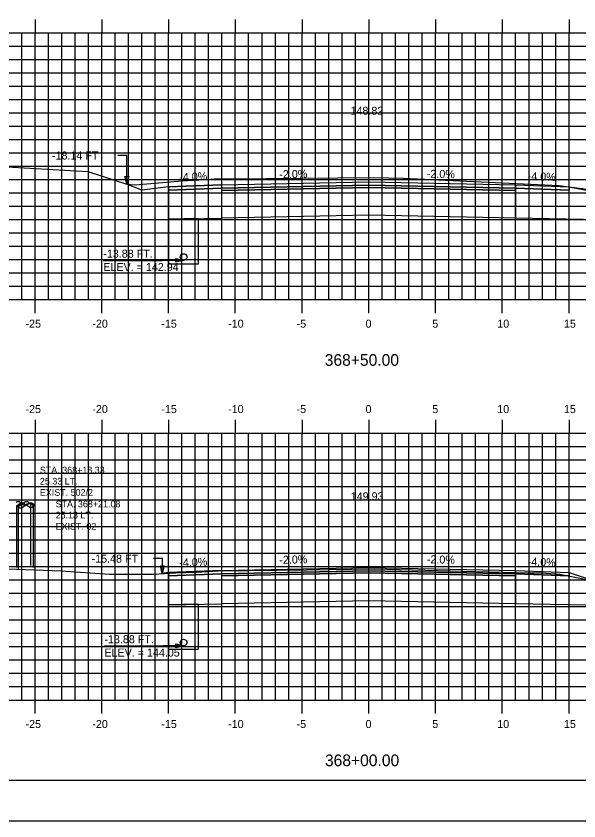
# Model space of a CAD drawing. Extents: x 1147855 to 1148025, y 608981 to 609091.
# Drawn here: x 1147911.8 to 1147953.9, y 608981.3 to 609041.6 of the extents above; entities that cross this region are included whole.
import ezdxf

# ---------------------------------------------------------------- set-up
doc = ezdxf.new("R2010")
doc.units = 0
for name, color, linetype in [('ANNOTATION', 7, 'Continuous'), ('BORDER', 7, 'Continuous'), ('D_Drainage_Underdrain', 7, 'Continuous'), ('D_Drainage_Underdrain_06in', 7, 'Continuous'), ('D_Roadway_Centerline', 7, 'Continuous'), ('D_Roadway_Centerline_Text', 7, 'Continuous'), ('D_Roadway_Edge_Shoulder', 7, 'Continuous'), ('D_Roadway_Edge_TW', 7, 'Continuous'), ('D_Roadway_Pavement', 7, 'Continuous'), ('D_Roadway_SlopeLines', 7, 'Continuous'), ('D_Roadway_SubGrade', 7, 'Continuous'), ('D_Text_Monospaced', 7, 'Continuous'), ('D_Text_Standard', 7, 'Continuous'), ('D_Utilities_Pole_Joint', 7, 'Continuous'), ('H_V ANNOTATION', 7, 'Continuous'), ('MAJOR', 7, 'Continuous'), ('MINOR', 7, 'Continuous'), ('PLOT BOUNDARY', 7, 'Continuous'), ('S_Roadway_Centerline', 7, 'Continuous'), ('S_Utilities_Pole_Power', 7, 'Continuous')]:
    doc.layers.add(name, color=color, linetype=linetype)

msp = doc.modelspace()

# ---------------------------------------------------------------- linework, layer by layer
for points in [[(1147923.21, 609028.779), (1147923.211, 609028.779), (1147927.211, 609028.939), (1147938.211, 609029.159), (1147949.211, 609028.939), (1147953.211, 609028.779), (1147966.938, 609026.085), (1147967.48, 609025.978), (1147968.704, 609026.54), (1147969.928, 609026.999), (1147971.152, 609027.357), (1147972.377, 609027.613)], [(1147922.727, 608999.809), (1147923.21, 608999.889), (1147923.211, 608999.889), (1147927.211, 609000.049), (1147938.211, 609000.269), (1147949.211, 609000.049), (1147953.211, 608999.889), (1147960.934, 608997.315), (1147963.934, 608996.315), (1147963.962, 608996.329), (1147965.212, 608996.889), (1147966.462, 608997.318), (1147967.712, 608997.616), (1147968.962, 608997.784)]]:
    msp.add_lwpolyline(points)
at = {"layer": 'BORDER'}
msp.add_lwpolyline([(1147863.211, 608984.335), (1148023.211, 608984.335), (1148023.211, 609089.335), (1147863.211, 609089.335)], close=True, dxfattribs=at)
at = {"layer": 'D_Drainage_Underdrain'}
for points in [[(1147923.211, 609026.359), (1147923.211, 609023.029), (1147925.461, 609023.029), (1147925.461, 609026.404)], [(1147923.211, 608997.469), (1147923.211, 608994.139), (1147925.461, 608994.139), (1147925.461, 608997.514)]]:
    msp.add_lwpolyline(points, close=True, dxfattribs=at)
at = {"layer": 'D_Drainage_Underdrain_06in'}
for points in [[(1147924.336, 609023.779), (1147924.413, 609023.767), (1147924.482, 609023.731), (1147924.538, 609023.676), (1147924.573, 609023.606), (1147924.586, 609023.529), (1147924.573, 609023.452), (1147924.538, 609023.382), (1147924.482, 609023.327), (1147924.413, 609023.291), (1147924.336, 609023.279), (1147924.258, 609023.291), (1147924.189, 609023.327), (1147924.133, 609023.382), (1147924.098, 609023.452), (1147924.086, 609023.529), (1147924.098, 609023.606), (1147924.133, 609023.676), (1147924.189, 609023.731), (1147924.258, 609023.767)], [(1147924.336, 608994.889), (1147924.413, 608994.877), (1147924.482, 608994.841), (1147924.538, 608994.786), (1147924.573, 608994.716), (1147924.586, 608994.639), (1147924.573, 608994.562), (1147924.538, 608994.492), (1147924.482, 608994.437), (1147924.413, 608994.401), (1147924.336, 608994.389), (1147924.258, 608994.401), (1147924.189, 608994.437), (1147924.133, 608994.492), (1147924.098, 608994.562), (1147924.086, 608994.639), (1147924.098, 608994.716), (1147924.133, 608994.786), (1147924.189, 608994.841), (1147924.258, 608994.877)]]:
    msp.add_lwpolyline(points, close=True, dxfattribs=at)
at = {"layer": 'D_Roadway_Edge_Shoulder'}
for points in [[(1147927.211, 609028.939), (1147923.211, 609028.779), (1147923.211, 609028.529), (1147927.211, 609028.689)], [(1147949.211, 609028.939), (1147953.211, 609028.779), (1147953.211, 609028.529), (1147949.211, 609028.689)], [(1147927.211, 609000.049), (1147923.211, 608999.889), (1147923.211, 608999.639), (1147927.211, 608999.799)], [(1147949.211, 609000.049), (1147953.211, 608999.889), (1147953.211, 608999.639), (1147949.211, 608999.799)]]:
    msp.add_lwpolyline(points, close=True, dxfattribs=at)
at = {"layer": 'D_Roadway_Edge_TW'}
for points in [[(1147927.211, 609028.689), (1147927.211, 609028.939), (1147938.211, 609029.159), (1147949.211, 609028.939), (1147949.211, 609028.689), (1147938.211, 609028.909)], [(1147927.211, 608999.799), (1147927.211, 609000.049), (1147938.211, 609000.269), (1147949.211, 609000.049), (1147949.211, 608999.799), (1147938.211, 609000.019)]]:
    msp.add_lwpolyline(points, close=True, dxfattribs=at)
at = {"layer": 'D_Roadway_Pavement'}
for points in [[(1147927.211, 609028.523), (1147927.211, 609028.689), (1147938.211, 609028.909), (1147949.211, 609028.689), (1147949.211, 609028.523), (1147938.211, 609028.743)], [(1147927.211, 608999.633), (1147927.211, 608999.799), (1147938.211, 609000.019), (1147949.211, 608999.799), (1147949.211, 608999.633), (1147938.211, 608999.853)]]:
    msp.add_lwpolyline(points, close=True, dxfattribs=at)
at = {"layer": 'D_Roadway_SlopeLines'}
for p, q in [((1147921.211, 609028.529), (1147920.071, 609028.98)), ((1147923.211, 609028.779), (1147921.211, 609028.529))]:
    msp.add_line(p, q, dxfattribs=at)
msp.add_lwpolyline([(1147923.211, 608999.889), (1147922.727, 608999.809)], dxfattribs=at)
at = {"layer": 'D_Roadway_SubGrade'}
for points in [[(1147923.21, 609027.779), (1147923.211, 609026.359), (1147927.211, 609026.439), (1147927.211, 609028.523), (1147927.211, 609028.689), (1147923.211, 609028.529), (1147923.211, 609028.779), (1147923.21, 609028.779)], [(1147927.211, 609026.439), (1147927.211, 609028.523), (1147938.211, 609028.743), (1147949.211, 609028.523), (1147949.211, 609026.439), (1147938.211, 609026.659)], [(1147949.211, 609028.523), (1147949.211, 609028.689), (1147953.211, 609028.529), (1147953.211, 609028.779), (1147953.211, 609028.779), (1147966.938, 609026.085), (1147949.211, 609026.439)], [(1147927.211, 608999.633), (1147927.211, 608999.799), (1147923.211, 608999.639), (1147923.211, 608999.889), (1147923.21, 608999.889), (1147923.211, 608997.469), (1147927.211, 608997.549)], [(1147927.211, 608997.549), (1147927.211, 608999.633), (1147938.211, 608999.853), (1147949.211, 608999.633), (1147949.211, 608997.549), (1147938.211, 608997.769)], [(1147949.211, 608999.633), (1147949.211, 608999.799), (1147953.211, 608999.639), (1147953.211, 608999.889), (1147953.211, 608999.889), (1147960.934, 608997.315), (1147949.211, 608997.549)]]:
    msp.add_lwpolyline(points, close=True, dxfattribs=at)
at = {"layer": 'D_Text_Standard'}
for p, q in [((1147918.325, 609023.279), (1147922.739, 609023.279)), ((1147918.407, 608994.389), (1147922.821, 608994.389))]:
    msp.add_line(p, q, dxfattribs=at)
for points in [[(1147920.074, 609028.979), (1147920.09, 609031.136), (1147919.41, 609031.136)], [(1147924.336, 609023.279), (1147923.419, 609023.279), (1147922.739, 609023.279)], [(1147922.727, 608999.809), (1147922.758, 609000.928), (1147922.078, 609000.928)], [(1147924.336, 608994.389), (1147923.501, 608994.389), (1147922.821, 608994.389)]]:
    msp.add_lwpolyline(points, dxfattribs=at)
for points in [[(1147920.074, 609028.979), (1147919.933, 609029.563), (1147920.224, 609029.56)], [(1147924.336, 609023.279), (1147923.753, 609023.134), (1147923.753, 609023.425)], [(1147922.727, 608999.809), (1147922.597, 609000.394), (1147922.888, 609000.386)], [(1147924.336, 608994.389), (1147923.753, 608994.244), (1147923.753, 608994.535)]]:
    msp.add_lwpolyline(points, close=True, dxfattribs=at)
at = {"layer": 'D_Utilities_Pole_Joint'}
for p, q in [((1147911.961, 609004.934), (1147912.117, 609005.044)), ((1147912.429, 609005.044), (1147912.585, 609004.934)), ((1147912.741, 609005.044), (1147912.585, 609004.934)), ((1147913.211, 609004.934), (1147913.054, 609005.044)), ((1147911.961, 609000.176), (1147911.961, 609004.934)), ((1147912.585, 609004.934), (1147912.741, 609004.823)), ((1147913.054, 609004.823), (1147913.211, 609004.934)), ((1147913.211, 609000.176), (1147913.211, 609004.934))]:
    msp.add_line(p, q, dxfattribs=at)
for centre, start, end in [((1147912.273, 609004.823), 90, 125.26439), ((1147912.273, 609004.823), 54.73561, 90), ((1147912.898, 609004.823), 90, 125.26439), ((1147912.898, 609004.823), 54.73561, 90), ((1147912.898, 609005.044), 234.73561, 270), ((1147912.898, 609005.044), 270, 305.26439)]:
    msp.add_arc(centre, 0.271, start, end, dxfattribs=at)
at = {"layer": 'MAJOR'}
for p, q in [((1147913.211, 609041.337), (1147913.211, 609040.335)), ((1147918.211, 609041.337), (1147918.211, 609040.335)), ((1147923.211, 609041.337), (1147923.211, 609040.335)), ((1147928.211, 609041.337), (1147928.211, 609040.335)), ((1147933.211, 609041.337), (1147933.211, 609040.335)), ((1147938.211, 609041.337), (1147938.211, 609040.335)), ((1147943.211, 609041.337), (1147943.211, 609040.335)), ((1147948.211, 609041.337), (1147948.211, 609040.335)), ((1147953.211, 609041.337), (1147953.211, 609040.335)), ((1147868.211, 609040.335), (1148008.211, 609040.335)), ((1147868.211, 609040.335), (1148008.211, 609040.335)), ((1147913.211, 609020.335), (1147913.211, 609040.335)), ((1147918.211, 609020.335), (1147918.211, 609040.335)), ((1147923.211, 609020.335), (1147923.211, 609040.335)), ((1147928.211, 609020.335), (1147928.211, 609040.335)), ((1147933.211, 609020.335), (1147933.211, 609040.335)), ((1147938.211, 609020.335), (1147938.211, 609040.335)), ((1147943.211, 609020.335), (1147943.211, 609040.335)), ((1147948.211, 609020.335), (1147948.211, 609040.335)), ((1147953.211, 609020.335), (1147953.211, 609040.335)), ((1147868.211, 609035.335), (1148008.211, 609035.335)), ((1147868.211, 609030.335), (1148008.211, 609030.335)), ((1147868.211, 609025.335), (1148008.211, 609025.335)), ((1147868.211, 609020.335), (1148008.211, 609020.335)), ((1147868.211, 609020.335), (1148008.211, 609020.335)), ((1147913.211, 609019.333), (1147913.211, 609020.335)), ((1147918.211, 609019.333), (1147918.211, 609020.335)), ((1147923.211, 609019.333), (1147923.211, 609020.335)), ((1147928.211, 609019.333), (1147928.211, 609020.335)), ((1147933.211, 609019.333), (1147933.211, 609020.335)), ((1147938.211, 609019.333), (1147938.211, 609020.335)), ((1147943.211, 609019.333), (1147943.211, 609020.335)), ((1147948.211, 609019.333), (1147948.211, 609020.335)), ((1147953.211, 609019.333), (1147953.211, 609020.335)), ((1147913.211, 609011.337), (1147913.211, 609010.335)), ((1147918.211, 609011.337), (1147918.211, 609010.335)), ((1147923.211, 609011.337), (1147923.211, 609010.335)), ((1147928.211, 609011.337), (1147928.211, 609010.335)), ((1147933.211, 609011.337), (1147933.211, 609010.335)), ((1147938.211, 609011.337), (1147938.211, 609010.335)), ((1147943.211, 609011.337), (1147943.211, 609010.335)), ((1147948.211, 609011.337), (1147948.211, 609010.335)), ((1147953.211, 609011.337), (1147953.211, 609010.335)), ((1147868.211, 609010.335), (1148008.211, 609010.335)), ((1147868.211, 609010.335), (1148008.211, 609010.335)), ((1147913.211, 608990.335), (1147913.211, 609010.335)), ((1147918.211, 608990.335), (1147918.211, 609010.335)), ((1147923.211, 608990.335), (1147923.211, 609010.335)), ((1147928.211, 608990.335), (1147928.211, 609010.335)), ((1147933.211, 608990.335), (1147933.211, 609010.335)), ((1147938.211, 608990.335), (1147938.211, 609010.335)), ((1147943.211, 608990.335), (1147943.211, 609010.335)), ((1147948.211, 608990.335), (1147948.211, 609010.335)), ((1147953.211, 608990.335), (1147953.211, 609010.335)), ((1147868.211, 609005.335), (1148008.211, 609005.335)), ((1147868.211, 609000.335), (1148008.211, 609000.335)), ((1147868.211, 608995.335), (1148008.211, 608995.335)), ((1147868.211, 608990.335), (1148008.211, 608990.335)), ((1147868.211, 608990.335), (1148008.211, 608990.335)), ((1147913.211, 608989.333), (1147913.211, 608990.335)), ((1147918.211, 608989.333), (1147918.211, 608990.335)), ((1147923.211, 608989.333), (1147923.211, 608990.335)), ((1147928.211, 608989.333), (1147928.211, 608990.335)), ((1147933.211, 608989.333), (1147933.211, 608990.335)), ((1147938.211, 608989.333), (1147938.211, 608990.335)), ((1147943.211, 608989.333), (1147943.211, 608990.335)), ((1147948.211, 608989.333), (1147948.211, 608990.335)), ((1147953.211, 608989.333), (1147953.211, 608990.335))]:
    msp.add_line(p, q, dxfattribs=at)
at = {"layer": 'MINOR'}
for p, q in [((1147912.211, 609020.335), (1147912.211, 609040.335)), ((1147914.211, 609020.335), (1147914.211, 609040.335)), ((1147915.211, 609020.335), (1147915.211, 609040.335)), ((1147916.211, 609020.335), (1147916.211, 609040.335)), ((1147917.211, 609020.335), (1147917.211, 609040.335)), ((1147919.211, 609020.335), (1147919.211, 609040.335)), ((1147920.211, 609020.335), (1147920.211, 609040.335)), ((1147921.211, 609020.335), (1147921.211, 609040.335)), ((1147922.211, 609020.335), (1147922.211, 609040.335)), ((1147924.211, 609020.335), (1147924.211, 609040.335)), ((1147925.211, 609020.335), (1147925.211, 609040.335)), ((1147926.211, 609020.335), (1147926.211, 609040.335)), ((1147927.211, 609020.335), (1147927.211, 609040.335)), ((1147929.211, 609020.335), (1147929.211, 609040.335)), ((1147930.211, 609020.335), (1147930.211, 609040.335)), ((1147931.211, 609020.335), (1147931.211, 609040.335)), ((1147932.211, 609020.335), (1147932.211, 609040.335)), ((1147934.211, 609020.335), (1147934.211, 609040.335)), ((1147935.211, 609020.335), (1147935.211, 609040.335)), ((1147936.211, 609020.335), (1147936.211, 609040.335)), ((1147937.211, 609020.335), (1147937.211, 609040.335)), ((1147939.211, 609020.335), (1147939.211, 609040.335)), ((1147940.211, 609020.335), (1147940.211, 609040.335)), ((1147941.211, 609020.335), (1147941.211, 609040.335)), ((1147942.211, 609020.335), (1147942.211, 609040.335)), ((1147944.211, 609020.335), (1147944.211, 609040.335)), ((1147945.211, 609020.335), (1147945.211, 609040.335)), ((1147946.211, 609020.335), (1147946.211, 609040.335)), ((1147947.211, 609020.335), (1147947.211, 609040.335)), ((1147949.211, 609020.335), (1147949.211, 609040.335)), ((1147950.211, 609020.335), (1147950.211, 609040.335)), ((1147951.211, 609020.335), (1147951.211, 609040.335)), ((1147952.211, 609020.335), (1147952.211, 609040.335)), ((1147868.211, 609039.335), (1148008.211, 609039.335)), ((1147868.211, 609038.335), (1148008.211, 609038.335)), ((1147868.211, 609037.335), (1148008.211, 609037.335)), ((1147868.211, 609036.335), (1148008.211, 609036.335)), ((1147868.211, 609034.335), (1148008.211, 609034.335)), ((1147868.211, 609033.335), (1148008.211, 609033.335)), ((1147868.211, 609032.335), (1148008.211, 609032.335)), ((1147868.211, 609031.335), (1148008.211, 609031.335)), ((1147868.211, 609029.335), (1148008.211, 609029.335)), ((1147868.211, 609028.335), (1148008.211, 609028.335)), ((1147868.211, 609027.335), (1148008.211, 609027.335)), ((1147868.211, 609026.335), (1148008.211, 609026.335)), ((1147868.211, 609024.335), (1148008.211, 609024.335)), ((1147868.211, 609023.335), (1148008.211, 609023.335)), ((1147868.211, 609022.335), (1148008.211, 609022.335)), ((1147868.211, 609021.335), (1148008.211, 609021.335)), ((1147912.211, 608990.335), (1147912.211, 609010.335)), ((1147914.211, 608990.335), (1147914.211, 609010.335)), ((1147915.211, 608990.335), (1147915.211, 609010.335)), ((1147916.211, 608990.335), (1147916.211, 609010.335)), ((1147917.211, 608990.335), (1147917.211, 609010.335)), ((1147919.211, 608990.335), (1147919.211, 609010.335)), ((1147920.211, 608990.335), (1147920.211, 609010.335)), ((1147921.211, 608990.335), (1147921.211, 609010.335)), ((1147922.211, 608990.335), (1147922.211, 609010.335)), ((1147924.211, 608990.335), (1147924.211, 609010.335)), ((1147925.211, 608990.335), (1147925.211, 609010.335)), ((1147926.211, 608990.335), (1147926.211, 609010.335)), ((1147927.211, 608990.335), (1147927.211, 609010.335)), ((1147929.211, 608990.335), (1147929.211, 609010.335)), ((1147930.211, 608990.335), (1147930.211, 609010.335)), ((1147931.211, 608990.335), (1147931.211, 609010.335)), ((1147932.211, 608990.335), (1147932.211, 609010.335)), ((1147934.211, 608990.335), (1147934.211, 609010.335)), ((1147935.211, 608990.335), (1147935.211, 609010.335)), ((1147936.211, 608990.335), (1147936.211, 609010.335)), ((1147937.211, 608990.335), (1147937.211, 609010.335)), ((1147939.211, 608990.335), (1147939.211, 609010.335)), ((1147940.211, 608990.335), (1147940.211, 609010.335)), ((1147941.211, 608990.335), (1147941.211, 609010.335)), ((1147942.211, 608990.335), (1147942.211, 609010.335)), ((1147944.211, 608990.335), (1147944.211, 609010.335)), ((1147945.211, 608990.335), (1147945.211, 609010.335)), ((1147946.211, 608990.335), (1147946.211, 609010.335)), ((1147947.211, 608990.335), (1147947.211, 609010.335)), ((1147949.211, 608990.335), (1147949.211, 609010.335)), ((1147950.211, 608990.335), (1147950.211, 609010.335)), ((1147951.211, 608990.335), (1147951.211, 609010.335)), ((1147952.211, 608990.335), (1147952.211, 609010.335)), ((1147868.211, 609009.335), (1148008.211, 609009.335)), ((1147868.211, 609008.335), (1148008.211, 609008.335)), ((1147868.211, 609007.335), (1148008.211, 609007.335)), ((1147868.211, 609006.335), (1148008.211, 609006.335)), ((1147868.211, 609004.335), (1148008.211, 609004.335)), ((1147868.211, 609003.335), (1148008.211, 609003.335)), ((1147868.211, 609002.335), (1148008.211, 609002.335)), ((1147868.211, 609001.335), (1148008.211, 609001.335)), ((1147868.211, 608999.335), (1148008.211, 608999.335)), ((1147868.211, 608998.335), (1148008.211, 608998.335)), ((1147868.211, 608997.335), (1148008.211, 608997.335)), ((1147868.211, 608996.335), (1148008.211, 608996.335)), ((1147868.211, 608994.335), (1148008.211, 608994.335)), ((1147868.211, 608993.335), (1148008.211, 608993.335)), ((1147868.211, 608992.335), (1148008.211, 608992.335)), ((1147868.211, 608991.335), (1148008.211, 608991.335))]:
    msp.add_line(p, q, dxfattribs=at)
at = {"layer": 'PLOT BOUNDARY'}
msp.add_lwpolyline([(1147855.117, 608981.276), (1148025.117, 608981.276), (1148025.117, 609091.276), (1147855.117, 609091.276)], close=True, dxfattribs=at)
at = {"layer": 'S_Roadway_Centerline'}
for points in [[(1147905.033, 609030.646), (1147917.167, 609029.936), (1147920.074, 609028.979), (1147920.713, 609028.933), (1147923.925, 609029.216), (1147924.199, 609029.231), (1147926.359, 609029.359), (1147926.651, 609029.377), (1147927.806, 609029.391), (1147938.591, 609029.489), (1147940.789, 609029.431), (1147952.444, 609028.899), (1147954.159, 609028.669), (1147954.197, 609028.662), (1147954.21, 609028.663), (1147954.245, 609028.651), (1147963.64, 609026.518), (1147963.717, 609026.515), (1147965.429, 609026.412), (1147966.055, 609026.554), (1147974.498, 609027.968), (1147978.677, 609028.23), (1147979.275, 609028.271)], [(1147903.402, 609000.314), (1147911.816, 609000.149), (1147915.16, 609000.018), (1147918.794, 608999.761), (1147922.073, 608999.773), (1147923.723, 608999.863), (1147925.309, 608999.916), (1147926.955, 609000.021), (1147933.547, 609000.1), (1147938.607, 609000.171), (1147945.257, 608999.995), (1147950.145, 608999.868), (1147951.153, 608999.855), (1147952.52, 608999.773), (1147961.597, 608997.939), (1147962.723, 608997.73), (1147966.96, 608997.559), (1147967.211, 608997.54), (1147967.577, 608997.583), (1147974.272, 608998.555), (1147974.652, 608998.571), (1147978.833, 608998.728)]]:
    msp.add_lwpolyline(points, dxfattribs=at)
at = {"layer": 'S_Utilities_Pole_Power'}
for p, q in [((1147912.103, 609005.135), (1147912.26, 609005.024)), ((1147912.26, 609005.024), (1147912.103, 609004.913)), ((1147912.416, 609005.135), (1147912.26, 609005.024)), ((1147912.885, 609005.024), (1147912.729, 609005.135)), ((1147912.885, 609000.405), (1147912.888, 609005.024)), ((1147911.834, 609004.892), (1147911.99, 609005.002)), ((1147911.834, 609000.273), (1147911.837, 609004.892)), ((1147911.99, 609004.781), (1147911.834, 609004.892)), ((1147912.302, 609005.002), (1147912.459, 609004.892)), ((1147912.459, 609004.892), (1147912.302, 609004.781)), ((1147912.615, 609005.002), (1147912.459, 609004.892)), ((1147913.084, 609004.892), (1147912.928, 609005.002)), ((1147913.084, 609000.273), (1147913.087, 609004.892))]:
    msp.add_line(p, q, dxfattribs=at)
for centre, start, end in [((1147911.947, 609004.914), 90, 125.26439), ((1147911.947, 609004.914), 54.73561, 90), ((1147912.146, 609004.782), 90, 125.26439), ((1147912.146, 609004.782), 54.73561, 90), ((1147912.572, 609004.914), 90, 125.26439), ((1147912.572, 609004.914), 54.73561, 90), ((1147912.771, 609004.782), 90, 125.26439), ((1147912.771, 609004.782), 54.73561, 90), ((1147911.947, 609005.135), 234.73561, 270), ((1147911.947, 609005.135), 270, 305.26439), ((1147912.146, 609005.003), 234.73561, 270), ((1147912.146, 609005.003), 270, 305.26439)]:
    msp.add_arc(centre, 0.271, start, end, dxfattribs=at)

# ---------------------------------------------------------------- texts
at = {"layer": 'ANNOTATION'}
for s, rotation, p in [('-4.0%', 2.29061, (1147924.026, 609029.213)), ('-2.0%', 1.14576, (1147931.514, 609029.425)), ('-2.0%', 358.85424, (1147942.554, 609029.473)), ('-4.0%', 357.70939, (1147950.106, 609029.304)), ('-4.0%', 2.29061, (1147924.026, 609000.323)), ('-2.0%', 1.14576, (1147931.514, 609000.536)), ('-2.0%', 358.85424, (1147942.554, 609000.583)), ('-4.0%', 357.70939, (1147950.106, 609000.414))]:
    msp.add_text(s, height=0.6, rotation=rotation, dxfattribs=at).set_placement(p)
at = {"layer": 'D_Roadway_Centerline'}
for s, p in [('C', (1147938.205, 609029.159)), ('L', (1147938.211, 609029.152)), ('C', (1147938.205, 609000.269)), ('L', (1147938.211, 609000.262))]:
    msp.add_text(s, height=0.0146, dxfattribs=at).set_placement(p)
at = {"layer": 'D_Roadway_Centerline_Text'}
for s, p in [('148.82', (1147936.843, 609034.191)), ('149.93', (1147936.86, 609005.301))]:
    msp.add_text(s, height=0.6, dxfattribs=at).set_placement(p)
at = {"layer": 'D_Text_Monospaced'}
for s, height, p in [('STA. 368+18.33', 0.49998, (1147913.573, 609007.313)), ('25.33 LT.', 0.5, (1147913.573, 609006.479)), ('EXIST. 502/2', 0.49998, (1147913.573, 609005.639)), ('STA. 368+21.08', 0.49998, (1147914.751, 609004.771)), ('25.13 LT.', 0.5, (1147914.751, 609003.937)), ('EXIST. 02', 0.5, (1147914.751, 609003.097))]:
    msp.add_text(s, height=height, dxfattribs=at).set_placement(p)
at = {"layer": 'D_Text_Standard'}
for s, p in [('-18.14 FT', (1147914.48, 609030.836)), ('-13.88 FT.', (1147918.325, 609023.479)), ('ELEV. = 142.94', (1147918.325, 609022.479)), ('-15.48 FT', (1147917.447, 609000.628)), ('-13.88 FT.', (1147918.407, 608994.589)), ('ELEV. = 144.05', (1147918.407, 608993.589))]:
    msp.add_text(s, height=0.6, dxfattribs=at).set_placement(p)
at = {"layer": 'H_V ANNOTATION'}
for s, height, p in [('-25', 0.6, (1147912.496, 609018.235)), ('-20', 0.6, (1147917.504, 609018.235)), ('-15', 0.6, (1147922.667, 609018.235)), ('-10', 0.6, (1147927.675, 609018.235)), ('-5', 0.6, (1147932.801, 609018.235)), ('0', 0.6, (1147937.97, 609018.235)), ('5', 0.6, (1147942.962, 609018.235)), ('10', 0.6, (1147947.836, 609018.235)), ('15', 0.6, (1147952.828, 609018.235)), ('368+50.00', 0.875, (1147934.91, 609015.378)), ('-25', 0.6, (1147912.496, 609011.835)), ('-20', 0.6, (1147917.504, 609011.835)), ('-15', 0.6, (1147922.667, 609011.835)), ('-10', 0.6, (1147927.675, 609011.835)), ('-5', 0.6, (1147932.801, 609011.835)), ('0', 0.6, (1147937.97, 609011.835)), ('5', 0.6, (1147942.962, 609011.835)), ('10', 0.6, (1147947.836, 609011.835)), ('15', 0.6, (1147952.828, 609011.835)), ('-25', 0.6, (1147912.496, 608988.235)), ('-20', 0.6, (1147917.504, 608988.235)), ('-15', 0.6, (1147922.667, 608988.235)), ('-10', 0.6, (1147927.675, 608988.235)), ('-5', 0.6, (1147932.801, 608988.235)), ('0', 0.6, (1147937.97, 608988.235)), ('5', 0.6, (1147942.962, 608988.235)), ('10', 0.6, (1147947.836, 608988.235)), ('15', 0.6, (1147952.828, 608988.235)), ('368+00.00', 0.875, (1147934.925, 608985.378))]:
    msp.add_text(s, height=height, dxfattribs=at).set_placement(p)
at = {"layer": 'S_Roadway_Centerline'}
for s, p in [('C', (1147938.586, 609029.489)), ('L', (1147938.591, 609029.481)), ('C', (1147938.602, 609000.171)), ('L', (1147938.607, 609000.164))]:
    msp.add_text(s, height=0.0146, dxfattribs=at).set_placement(p)

doc.saveas('drawing.dxf')
